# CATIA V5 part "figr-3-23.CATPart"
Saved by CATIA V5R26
Part number: figr-3-23
Bounding box of the stored display mesh (mm): x 0 to 0, y -2187335.75 to 2141537, z -681609 to 2530522.25
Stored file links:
  D:\_Deepak\CATIA\CATIA V5 2015 Parts Files\Part files\Partfiles\c03_catia_v5_6r2015_prt\figr-3-23.CATPart
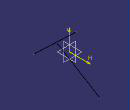
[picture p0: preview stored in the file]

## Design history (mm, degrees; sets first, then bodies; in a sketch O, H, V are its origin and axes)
Body1 (main body)
  Sketch1 on yz-plane, origin (0, 0, 0), H (0, 1, 0), V (0, 0, 1)
    line L1 through (-830059.7691, 1160197.0782) direction (0.7237, 0.6901)
    line L2 through (299240.8462, 476164.2676) direction (0.8467, -0.5321)
    line L3 (-18.0725, -9.9702) -> (3.3205, 10.401)
    line L4 (15.39, -12.4607) -> (-6.6544, 0.9026)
